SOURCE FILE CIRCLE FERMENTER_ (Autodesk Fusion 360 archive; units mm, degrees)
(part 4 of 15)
sketch "Schizzo1" plane through (-156.8, 0, 0) normal (-1, 0, 0) x axis (0, -1, 0)
  curve K1 (43.7015, -77.2094) -> (43.1419, -79.5252)
  curve K2 (45.0581, -79.5252) -> (44.4985, -77.2094)
  curve K3 (79.8015, 15.4906) -> (79.2419, 13.1748)
  curve K4 (81.1581, 13.1748) -> (80.5985, 15.4906)
  curve K5 (43.7015, 108.1906) -> (43.1419, 105.8748)
  curve K6 (45.0581, 105.8748) -> (44.4985, 108.1906)
  curve K7 (-0.3985, -77.2094) -> (-0.9581, -79.5252)
  curve K8 (0.9581, -79.5252) -> (0.3985, -77.2094)
  curve K9 (-44.4985, -77.2094) -> (-45.0581, -79.5252)
  curve K10 (-43.1419, -79.5252) -> (-43.7015, -77.2094)
  curve K11 (-44.4985, 108.1906) -> (-45.0581, 105.8748)
  curve K12 (-43.1419, 105.8748) -> (-43.7015, 108.1906)
  curve K13 (-0.3985, 108.1906) -> (-0.9581, 105.8748)
  curve K14 (0.9581, 105.8748) -> (0.3985, 108.1906)
  curve K15 (-80.5985, 15.4906) -> (-81.1581, 13.1748)
  curve K16 (-79.2419, 13.1748) -> (-79.8015, 15.4906)
  line L1 (65, 103.7507) -> (-65, 103.7507)
  curve K17 (77.2507, 91.5) -> (65, 103.7507)
  line L2 (77.2507, -63.5) -> (77.2507, 91.5)
  curve K18 (65, -75.7507) -> (77.2507, -63.5)
  line L3 (-65, -75.7507) -> (65, -75.7507)
  curve K19 (-77.2507, -63.5) -> (-65, -75.7507)
  line L4 (-77.2507, 91.5) -> (-77.2507, -63.5)
  curve K20 (-65, 103.7507) -> (-77.2507, 91.5)
  line L5 (-65, 111.4507) -> (65, 111.4507)
  curve K21 (-84.9507, 91.5) -> (-65, 111.4507)
  line L6 (-84.9507, -63.5) -> (-84.9507, 91.5)
  curve K22 (-65, -83.4507) -> (-84.9507, -63.5)
  line L7 (65, -83.4507) -> (-65, -83.4507)
  curve K23 (84.9507, -63.5) -> (65, -83.4507)
  line L8 (84.9507, 91.5) -> (84.9507, -63.5)
  curve K24 (65, 111.4507) -> (84.9507, 91.5)
  arc A1 centre (44.1, -78.7) radius 1.2645 clockwise from (45.0581, -79.5252) to (43.1419, -79.5252)
  arc A2 centre (80.2, 14) radius 1.2645 clockwise from (81.1581, 13.1748) to (79.2419, 13.1748)
  arc A3 centre (44.1, 106.7) radius 1.2645 clockwise from (45.0581, 105.8748) to (43.1419, 105.8748)
  arc A4 centre (0, -78.7) radius 1.2645 clockwise from (0.9581, -79.5252) to (-0.9581, -79.5252)
  arc A5 centre (-44.1, -78.7) radius 1.2645 clockwise from (-43.1419, -79.5252) to (-45.0581, -79.5252)
  arc A6 centre (-44.1, 106.7) radius 1.2645 clockwise from (-43.1419, 105.8748) to (-45.0581, 105.8748)
  arc A7 centre (0, 106.7) radius 1.2645 clockwise from (0.9581, 105.8748) to (-0.9581, 105.8748)
  arc A8 centre (-80.2, 14) radius 1.2645 clockwise from (-79.2419, 13.1748) to (-81.1581, 13.1748)
  circle C1 centre (81.5735, 71.5) radius 1.75
  circle C2 centre (81.5735, 71.5) radius 1.75
  circle C3 centre (81.5735, -43.5) radius 1.75
  circle C4 centre (-81.5735, -43.5) radius 1.75
  circle C5 centre (-81.5735, -43.5) radius 1.75
  circle C6 centre (-81.5735, 71.5) radius 1.75
  circle C7 centre (-81.5735, 71.5) radius 1.75
  arc A9 centre (-80.2, 14) radius 1.543 clockwise from (-80.5985, 15.4906) to (-79.8015, 15.4906)
  arc A10 centre (0, 106.7) radius 1.543 clockwise from (-0.3985, 108.1906) to (0.3985, 108.1906)
  arc A11 centre (-44.1, 106.7) radius 1.543 clockwise from (-44.4985, 108.1906) to (-43.7015, 108.1906)
  arc A12 centre (-44.1, -78.7) radius 1.543 clockwise from (-44.4985, -77.2094) to (-43.7015, -77.2094)
  arc A13 centre (0, -78.7) radius 1.543 clockwise from (-0.3985, -77.2094) to (0.3985, -77.2094)
  arc A14 centre (44.1, 106.7) radius 1.543 clockwise from (43.7015, 108.1906) to (44.4985, 108.1906)
  arc A15 centre (80.2, 14) radius 1.543 clockwise from (79.8015, 15.4906) to (80.5985, 15.4906)
  arc A16 centre (44.1, -78.7) radius 1.543 clockwise from (43.7015, -77.2094) to (44.4985, -77.2094)
extrude "Estrusione1" cut sketch "Schizzo1" profile of C1 C2 C3 C4 C5 C6 C7 against normal blind 3
offset_faces "FacceDiOffset1" distance -0.5
sketch "Schizzo2" plane through (0, 0, -63.5) normal (0, 0, -1) x axis (-1, 0, 0)
  line L1 (156.8, -77.2507) -> (156.8, -84.9507)
  line L2 (156.8, 84.9507) -> (156.8, 77.2507)
  line L3 (180, 88.4) -> (160, 88.4)
  line L4 (153.8, 84.9507) -> (156.8, 84.9507)
  curve K1 (160, 86.8) -> (153.8, 85.2507)
  line L5 (160, -86.8) -> (160, -88.4)
  line L6 (160, 88.4) -> (160, 86.8)
  curve K2 (160, 86.55) -> (153.9051, 85.0239)
  line L7 (153.9051, 85.0239) -> (153.8, 84.9507)
  line L8 (160, 88.4) -> (160, 86.55)
  line L9 (156.8, 77.2507) -> (153.8, 77.2507)
  curve K3 (157.8, 77.2507) -> (153.8, 77.2507)
  curve K4 (160.8, 82.6455) -> (157.8, 77.2507)
  curve K5 (164, 88.4) -> (160.8, 82.6455)
  curve K6 (168, 88.4) -> (164, 88.4)
  curve K7 (168, 88.4) -> (153.8, 77.2507)
  line L10 (156.8, 77.2507) -> (153.8, 77.2507)
  line L11 (156.8, 78.3845) -> (156.8, 77.2507)
  point P9 (153.8, 84.9507)
  point P18 (153.8, 84.9507)
  point P6 (160, 88.4)
  point P19 (160, 88.4)
  point P24 (164, 88.4)
  point P25 (168, 88.4)
  point P20 (153.8, 77.2507)
  point P26 (153.8, 77.2507)
  point P21 (156.8, 77.2507)
  point P27 (156.8, 77.2507)
  point P4 (156.8, 77.2507)
  point P28 (156.8, 77.2507)
  point P29 (156.8, 78.3845)
  point P22 (157.8, 77.2507)
  point P23 (160.8, 82.6455)
  coincident P9 P18
  coincident P6 P19
  perpendicular L3 L8
  coincident L3 P24
  coincident L3 P25
  horizontal K3
  parallel K4 K5
  coincident P20 P26
  coincident P21 P27
  coincident P4 P28
  coincident K7 P29
  coincident L2 P29
  dimension "d1011" = 0.25
  dimension "d1014" distance P20 P22 = 4
  dimension "d1015" distance P24 P25 = 4
  dimension "d1016" distance P19 P24 = 4
  dimension "d1017" distance P22 P24 = 11.1493
  dimension "d1018" distance L2 P23 = 4
sweep "Sweep1" sketch "Schizzo2" TwistAngle 0 TaperAngle 0
sweep "Sweep2" sketch "Schizzo2" TwistAngle 0 TaperAngle 0
remove_body "RimuoviCorpo4"
sketch "Schizzo3" plane through (-160, 0, 0) normal (-1, 0, 0) x axis (0, -1, 0)
  line L1 (-65, 116.5) -> (65, 116.5)
  curve K1 (-65, 116.5) -> (-90, 91.5)
  line L2 (-90, -63.5) -> (-90, 91.5)
  curve K2 (-65, -88.5) -> (-90, -63.5)
  line L3 (65, -88.5) -> (-65, -88.5)
  curve K3 (65, -88.5) -> (90, -63.5)
  line L4 (90, 91.5) -> (90, -63.5)
  curve K4 (65, 116.5) -> (90, 91.5)
  line L5 (65, 114.9) -> (-65, 114.9)
  curve K5 (88.4, 91.5) -> (65, 114.9)
  line L6 (88.4, -63.5) -> (88.4, 91.5)
  curve K6 (88.4, -63.5) -> (65, -86.9)
  line L7 (-65, -86.9) -> (65, -86.9)
  curve K7 (-88.4, -63.5) -> (-65, -86.9)
  line L8 (-88.4, 91.5) -> (-88.4, -63.5)
  curve K8 (-88.4, 91.5) -> (-65, 114.9)
extrude "Estrusione2" add sketch "Schizzo3" along normal blind 20
chamfer "Smusso1" distance 0.8
sketch "Schizzo4" plane through (-148.4, 0, 0) normal (1, 0, 0) x axis (0, 1, 0)
  curve K1 (65, 110.4651) -> (83.9651, 91.5)
  line L1 (-65, 110.4651) -> (65, 110.4651)
  curve K2 (-83.9651, 91.5) -> (-65, 110.4651)
  line L2 (-83.9651, -63.5) -> (-83.9651, 91.5)
  curve K3 (-65, -82.4651) -> (-83.9651, -63.5)
  line L3 (65, -82.4651) -> (-65, -82.4651)
  curve K4 (83.9651, -63.5) -> (65, -82.4651)
  line L4 (83.9651, 91.5) -> (83.9651, -63.5)
  curve K5 (-76.5, -63.5) -> (-65, -75)
  line L5 (-76.5, 91.5) -> (-76.5, -63.5)
  curve K6 (-65, 103) -> (-76.5, 91.5)
  line L6 (65, 103) -> (-65, 103)
  curve K7 (76.5, 91.5) -> (65, 103)
  line L7 (76.5, -63.5) -> (76.5, 91.5)
  curve K8 (65, -75) -> (76.5, -63.5)
  line L8 (-65, -75) -> (65, -75)
  circle C1 centre (-44.1, -78.7) radius 3.35
  circle C2 centre (44.1, -78.7) radius 3.35
  circle C3 centre (0, -78.7) radius 3.35
  circle C4 centre (-44.1, 106.7) radius 3.35
  circle C5 centre (-80.2, 14) radius 3.35
  circle C6 centre (44.1, 106.7) radius 3.35
  circle C7 centre (0, 106.7) radius 3.35
  circle C8 centre (80.2, 14) radius 3.35
  circle C9 centre (-81.5735, 71.5) radius 1.75
  circle C10 centre (81.5735, 71.5) radius 1.75
  circle C11 centre (-81.5735, -43.5) radius 1.75
  circle C12 centre (81.5735, -43.5) radius 1.75
extrude "Estrusione3" cut sketch "Schizzo4" profile of C9 C10 C11 C12 against normal blind 75.727
work_plane "Piano di lavoro1" AlongDistance 3
remove_body "RimuoviCorpo6"
work_plane "Piano di lavoro2" AlongDistance -25
sketch "Schizzo7" plane through (0, 0, -63.5) normal (0, 0, -1) x axis (-1, 0, 0)
  line L1 (180, 88.4) -> (168, 88.4)
  curve K1 (168, 88.4) -> (156.8, 78.3845)
  curve K2 (156.8, 78.3845) -> (153.8, 77.2507)
  line L2 (180, 81.4) -> (180, 88.4)
  curve K3 (177, 81.4) -> (180, 81.4)
  curve K4 (174, 84.9) -> (177, 81.4)
  curve K5 (171, 88.4) -> (174, 84.9)
  curve K6 (168, 88.4) -> (171, 88.4)
  curve K7 (168, 88.4) -> (180, 81.4)
  point P11 (171, 88.4)
  point P3 (180, 88.4)
  point P12 (180, 88.4)
  point P8 (180, 81.4)
  point P9 (177, 81.4)
  point P5 (168, 88.4)
  point P10 (174, 84.9)
  perpendicular L1 L2
  coincident L1 P11
  horizontal K3
  parallel K4 K5
  coincident P3 P12
  dimension "d1051" distance P3 P8 = 7
  dimension "d1052" distance P8 P9 = 3
  dimension "d1053" distance P5 P11 = 3
  dimension "d1054" distance P10 K3 = 3.5 (= "d1051 / 2")
sketch "Schizzo6" plane through (-180, 0, 0) normal (-1, 0, 0) x axis (0, -1, 0)
  line L1 (65, 114.9) -> (-65, 114.9)
  curve K1 (88.4, 91.5) -> (65, 114.9)
  line L2 (88.4, -63.5) -> (88.4, 91.5)
  curve K2 (65, -86.9) -> (88.4, -63.5)
  line L3 (-65, -86.9) -> (65, -86.9)
  curve K3 (-88.4, -63.5) -> (-65, -86.9)
  line L4 (-88.4, 91.5) -> (-88.4, -63.5)
  curve K4 (-65, 114.9) -> (-88.4, 91.5)
  line L5 (90, 91.5) -> (90, -63.5)
  curve K5 (65, 116.5) -> (90, 91.5)
  line L6 (-65, 116.5) -> (65, 116.5)
  curve K6 (-90, 91.5) -> (-65, 116.5)
  line L7 (-90, -63.5) -> (-90, 91.5)
  curve K7 (-65, -88.5) -> (-90, -63.5)
  line L8 (65, -88.5) -> (-65, -88.5)
  curve K8 (90, -63.5) -> (65, -88.5)
  line L9 (-81.5735, 68.5) -> (-81.5735, 74.5)
  line L10 (-88.4, 60.4309) -> (-79.4522, 69.3787)
  line L11 (-88.4, 82.5691) -> (-79.4522, 73.6213)
  line L12 (-6.0795, 14) -> (-90, 14)
  line L13 (-88.4, -54.5691) -> (-79.4522, -45.6213)
  line L14 (-88.4, -32.4309) -> (-79.4522, -41.3787)
  circle C1 centre (-81.5735, -43.5) radius 1.75
  circle C2 centre (-81.5735, 71.5) radius 1.75
  arc A1 centre (-81.5735, 71.5) radius 3 clockwise from (-79.4522, 73.6213) to (-79.4522, 69.3787)
  arc A2 centre (-81.5735, -43.5) radius 3 clockwise from (-79.4522, -41.3787) to (-79.4522, -45.6213)
  point P20 (-81.5735, 71.5)
  point P24 (-88.4, 60.4309)
  point P26 (-88.4, 82.5691)
  point P27 (-90, 14)
  point P23 (-79.4522, 69.3787)
  point P32 (-79.4522, -41.3787)
  point P33 (-88.4, -32.4309)
  point P25 (-79.4522, 73.6213)
  point P29 (-79.4522, -45.6213)
  point P30 (-88.4, -54.5691)
  concentric C2 A1
  vertical L9
  coincident P20 L9
  coincident L4 P24
  coincident L4 P26
  tangent L11 A1
  tangent L10 A1
  midpoint L7 P27
  perpendicular L4 L12
  symmetric P23 L12 P32
  symmetric P24 L12 P33
  symmetric P25 L12 P29
  symmetric P26 L12 P30
  symmetric A1 L12 A2
  dimension "d1043" diameter A1 = 6
  dimension "d1044" angle L9 L10 = 135
  dimension "d1045" angle L9 L11 = 135
extrude "Estrusione5" add sketch "Schizzo6" profile of L4 C1 C2 A1 L10 L11 L13 A2 L14 to an object
mirror "Specchio1" mirrorStitchTolerance 0.1
sweep "Sweep3" sketch "Schizzo7" TwistAngle 0 TaperAngle 0
sketch "Schizzo8" plane through (-153.8, 0, 0) normal (1, 0, 0) x axis (0, 1, 0)
  line L1 (-84.9507, -63.5) -> (-84.9507, 91.5)
  curve K1 (-65, -83.4507) -> (-84.9507, -63.5)
  line L2 (65, -83.4507) -> (-65, -83.4507)
  curve K2 (84.9507, -63.5) -> (65, -83.4507)
  line L3 (84.9507, 91.5) -> (84.9507, -63.5)
  curve K3 (65, 111.4507) -> (84.9507, 91.5)
  line L4 (-65, 111.4507) -> (65, 111.4507)
  curve K4 (-84.9507, 91.5) -> (-65, 111.4507)
  curve K5 (81.1581, 13.1748) -> (80.5985, 15.4906)
  curve K6 (79.8015, 15.4906) -> (79.2419, 13.1748)
  curve K7 (-43.1419, -79.5252) -> (-43.7015, -77.2094)
  curve K8 (-44.4985, -77.2094) -> (-45.0581, -79.5252)
  curve K9 (0.9581, 105.8748) -> (0.3985, 108.1906)
  curve K10 (-0.3985, 108.1906) -> (-0.9581, 105.8748)
  curve K11 (0.9581, -79.5252) -> (0.3985, -77.2094)
  curve K12 (-0.3985, -77.2094) -> (-0.9581, -79.5252)
  curve K13 (-79.2419, 13.1748) -> (-79.8015, 15.4906)
  curve K14 (-80.5985, 15.4906) -> (-81.1581, 13.1748)
  curve K15 (-43.1419, 105.8748) -> (-43.7015, 108.1906)
  curve K16 (-44.4985, 108.1906) -> (-45.0581, 105.8748)
  curve K17 (45.0581, 105.8748) -> (44.4985, 108.1906)
  curve K18 (43.7015, 108.1906) -> (43.1419, 105.8748)
  curve K19 (45.0581, -79.5252) -> (44.4985, -77.2094)
  curve K20 (43.7015, -77.2094) -> (43.1419, -79.5252)
  line L5 (65, 103.7507) -> (-65, 103.7507)
  curve K21 (65, 103.7507) -> (77.2507, 91.5)
  line L6 (77.2507, -63.5) -> (77.2507, 91.5)
  curve K22 (77.2507, -63.5) -> (65, -75.7507)
  line L7 (-65, -75.7507) -> (65, -75.7507)
  curve K23 (-65, -75.7507) -> (-77.2507, -63.5)
  line L8 (-77.2507, 91.5) -> (-77.2507, -63.5)
  curve K24 (-77.2507, 91.5) -> (-65, 103.7507)
  circle C1 centre (-81.5735, 71.5) radius 2.25
  circle C2 centre (-81.5735, -43.5) radius 2.25
  circle C3 centre (81.5735, 71.5) radius 2.25
  circle C4 centre (81.5735, -43.5) radius 2.25
  arc A1 centre (80.2, 14) radius 1.2645 clockwise from (81.1581, 13.1748) to (79.2419, 13.1748)
  arc A2 centre (-44.1, -78.7) radius 1.2645 clockwise from (-43.1419, -79.5252) to (-45.0581, -79.5252)
  arc A3 centre (0, 106.7) radius 1.2645 clockwise from (0.9581, 105.8748) to (-0.9581, 105.8748)
  arc A4 centre (0, -78.7) radius 1.2645 clockwise from (0.9581, -79.5252) to (-0.9581, -79.5252)
  arc A5 centre (-80.2, 14) radius 1.2645 clockwise from (-79.2419, 13.1748) to (-81.1581, 13.1748)
  arc A6 centre (-44.1, 106.7) radius 1.2645 clockwise from (-43.1419, 105.8748) to (-45.0581, 105.8748)
  arc A7 centre (44.1, 106.7) radius 1.2645 clockwise from (45.0581, 105.8748) to (43.1419, 105.8748)
  arc A8 centre (44.1, -78.7) radius 1.2645 clockwise from (45.0581, -79.5252) to (43.1419, -79.5252)
  circle C5 centre (81.5735, -43.5) radius 1.75
  circle C6 centre (81.5735, 71.5) radius 1.75
  circle C7 centre (-81.5735, 71.5) radius 1.75
  circle C8 centre (-81.5735, 71.5) radius 2.25
  circle C9 centre (-81.5735, -43.5) radius 2.25
  circle C10 centre (-81.5735, -43.5) radius 1.75
  circle C11 centre (81.5735, -43.5) radius 2.25
  circle C12 centre (81.5735, 71.5) radius 2.25
  arc A9 centre (44.1, -78.7) radius 1.543 clockwise from (43.7015, -77.2094) to (44.4985, -77.2094)
  arc A10 centre (-44.1, 106.7) radius 1.543 clockwise from (-44.4985, 108.1906) to (-43.7015, 108.1906)
  arc A11 centre (0, 106.7) radius 1.543 clockwise from (-0.3985, 108.1906) to (0.3985, 108.1906)
  arc A12 centre (-80.2, 14) radius 1.543 clockwise from (-80.5985, 15.4906) to (-79.8015, 15.4906)
  arc A13 centre (80.2, 14) radius 1.543 clockwise from (79.8015, 15.4906) to (80.5985, 15.4906)
  arc A14 centre (44.1, 106.7) radius 1.543 clockwise from (43.7015, 108.1906) to (44.4985, 108.1906)
  arc A15 centre (0, -78.7) radius 1.543 clockwise from (-0.3985, -77.2094) to (0.3985, -77.2094)
  arc A16 centre (-44.1, -78.7) radius 1.543 clockwise from (-44.4985, -77.2094) to (-43.7015, -77.2094)
extrude "Estrusione6" cut sketch "Schizzo8" profile of C5 C6 C7 C10 against normal blind 84.147
extrude "Estrusione7" add sketch "Schizzo8" profile of C1 C2 C3 C4 C5 C6 C7 C8 C9 C10 C11 C12 against normal blind 3.228
fillet "Raccordo1" radius 3
sketch "Schizzo1" plane through (-180, 0, 0) normal (-1, 0, 0) x axis (0, -1, 0)
  line L1 (79.4522, 73.6213) -> (80.5213, 74.6904)
  line L2 (80.5213, 68.3096) -> (79.4522, 69.3787)
  curve K1 (80.5213, 68.3096) -> (81.4, 66.1882)
  line L3 (81.4, -38.1882) -> (81.4, 66.1882)
  curve K2 (81.4, -38.1882) -> (80.5213, -40.3096)
  line L4 (79.4522, -41.3787) -> (80.5213, -40.3096)
  line L5 (80.5213, -46.6904) -> (79.4522, -45.6213)
  curve K3 (80.5213, -46.6904) -> (81.4, -48.8118)
  line L6 (81.4, -63.5) -> (81.4, -48.8118)
  curve K4 (81.4, -63.5) -> (65, -79.9)
  line L7 (-65, -79.9) -> (65, -79.9)
  curve K5 (-65, -79.9) -> (-81.4, -63.5)
  line L8 (-81.4, -48.8118) -> (-81.4, -63.5)
  curve K6 (-81.4, -48.8118) -> (-80.5213, -46.6904)
  line L9 (-79.4522, -45.6213) -> (-80.5213, -46.6904)
  line L10 (-80.5213, -40.3096) -> (-79.4522, -41.3787)
  curve K7 (-80.5213, -40.3096) -> (-81.4, -38.1882)
  line L11 (-81.4, 66.1882) -> (-81.4, -38.1882)
  curve K8 (-81.4, 66.1882) -> (-80.5213, 68.3096)
  line L12 (-79.4522, 69.3787) -> (-80.5213, 68.3096)
  line L13 (-80.5213, 74.6904) -> (-79.4522, 73.6213)
  curve K9 (-80.5213, 74.6904) -> (-81.4, 76.8118)
  line L14 (-81.4, 91.5) -> (-81.4, 76.8118)
  curve K10 (-81.4, 91.5) -> (-65, 107.9)
  line L15 (65, 107.9) -> (-65, 107.9)
  curve K11 (65, 107.9) -> (81.4, 91.5)
  line L16 (81.4, 76.8118) -> (81.4, 91.5)
  curve K12 (81.4, 76.8118) -> (80.5213, 74.6904)
  line L17 (90, 91.5) -> (90, -63.5)
  curve K13 (65, 116.5) -> (90, 91.5)
  line L18 (-65, 116.5) -> (65, 116.5)
  curve K14 (-90, 91.5) -> (-65, 116.5)
  line L19 (-90, -63.5) -> (-90, 91.5)
  curve K15 (-65, -88.5) -> (-90, -63.5)
  line L20 (65, -88.5) -> (-65, -88.5)
  curve K16 (90, -63.5) -> (65, -88.5)
  line L21 (-36.4, 59.4) -> (36.4, 59.4)
  line L22 (-42.4, -25.4) -> (-42.4, 53.4)
  line L23 (36.4, -31.4) -> (-36.4, -31.4)
  line L24 (42.4, 53.4) -> (42.4, -25.4)
  line L25 (0, -88.5) -> (0, 116.5)
  line L26 (-42.9, -25.4) -> (-42.9, 53.4)
  line L27 (36.4, -31.9) -> (-36.4, -31.9)
  line L28 (42.9, 53.4) -> (42.9, -25.4)
  line L29 (-36.4, 59.9) -> (36.4, 59.9)
  line L30 (65, -86.5) -> (-65, -86.5)
  curve K17 (88, -63.5) -> (65, -86.5)
  line L31 (88, 91.5) -> (88, -63.5)
  curve K18 (65, 114.5) -> (88, 91.5)
  line L32 (-65, 114.5) -> (65, 114.5)
  line L33 (88, 82.1691) -> (80.5213, 74.6904)
  line L34 (88, 60.8309) -> (80.5213, 68.3096)
  line L35 (88, -32.8309) -> (80.5213, -40.3096)
  line L36 (88, -54.1691) -> (80.5213, -46.6904)
  arc A1 centre (81.5735, 71.5) radius 3 clockwise from (79.4522, 69.3787) to (79.4522, 73.6213)
  arc A2 centre (81.5735, -43.5) radius 3 clockwise from (79.4522, -45.6213) to (79.4522, -41.3787)
  arc A3 centre (-81.5735, -43.5) radius 3 clockwise from (-79.4522, -41.3787) to (-79.4522, -45.6213)
  arc A4 centre (-81.5735, 71.5) radius 3 clockwise from (-79.4522, 73.6213) to (-79.4522, 69.3787)
  circle C1 centre (81.5735, -43.5) radius 1.75
  circle C2 centre (-81.5735, -43.5) radius 1.75
  circle C3 centre (-81.5735, 71.5) radius 1.75
  circle C4 centre (81.5735, 71.5) radius 1.75
  arc A5 centre (-36.4, 53.4) radius 6 clockwise from (-42.4, 53.4) to (-36.4, 59.4)
  arc A6 centre (-36.4, -25.4) radius 6 clockwise from (-36.4, -31.4) to (-42.4, -25.4)
  arc A7 centre (36.4, -25.4) radius 6 clockwise from (42.4, -25.4) to (36.4, -31.4)
  arc A8 centre (36.4, 53.4) radius 6 clockwise from (36.4, 59.4) to (42.4, 53.4)
  arc A9 centre (-36.4, -25.4) radius 6.5 clockwise from (-36.4, -31.9) to (-42.9, -25.4)
  arc A10 centre (36.4, -25.4) radius 6.5 clockwise from (42.9, -25.4) to (36.4, -31.9)
  arc A11 centre (36.4, 53.4) radius 6.5 clockwise from (36.4, 59.9) to (42.9, 53.4)
  arc A12 centre (-36.4, 53.4) radius 6.5 clockwise from (-42.9, 53.4) to (-36.4, 59.9)
  point P58 (0, 116.5)
  point P59 (0, -88.5)
  point P2 (80.5213, 74.6904)
  point P78 (80.5213, 74.6904)
  point P79 (88, 82.1691)
  point P6 (80.5213, 68.3096)
  point P80 (80.5213, 68.3096)
  point P81 (88, 60.8309)
  point P9 (80.5213, -40.3096)
  point P82 (80.5213, -40.3096)
  point P83 (88, -32.8309)
  point P13 (80.5213, -46.6904)
  point P84 (80.5213, -46.6904)
  point P85 (88, -54.1691)
  midpoint L18 P58
  midpoint L20 P59
  coincident P2 P78
  coincident L31 P79
  coincident P6 P80
  coincident L31 P81
  coincident P9 P82
  coincident L31 P83
  coincident P13 P84
  coincident L31 P85
  dimension "d1067" = 0.5
  dimension "d1068" = -2
extrude "Estrusione1" new body sketch "Schizzo1" profile of L1 A1 L2 L4 A2 L5 L25 L28 L27 A10 A11 L29 K17 L30 L31 K18 L32 L33 L34 L35 L36 along normal blind 3
fillet "Raccordo1" radius 5
sketch "Schizzo2" plane through (-183, 0, 0) normal (-1, 0, 0) x axis (0, -1, 0)
  line L1 (79.4522, -45.6213) -> (86.5355, -52.7047)
  line L2 (86.5355, -34.2953) -> (79.4522, -41.3787)
  line L3 (88, 58.7598) -> (88, -30.7598)
  line L4 (79.4522, 69.3787) -> (86.5355, 62.2953)
  line L5 (86.5355, 80.7047) -> (79.4522, 73.6213)
  line L6 (88, 91.5) -> (88, 84.2402)
  curve K1 (65, 114.5) -> (88, 91.5)
  line L7 (0, 114.5) -> (65, 114.5)
  line L8 (0, 59.9) -> (0, 114.5)
  line L9 (36.4, 59.9) -> (0, 59.9)
  line L10 (42.9, -25.4) -> (42.9, 53.4)
  line L11 (0, -31.9) -> (36.4, -31.9)
  line L12 (0, -86.5) -> (0, -31.9)
  line L13 (65, -86.5) -> (0, -86.5)
  curve K2 (88, -63.5) -> (65, -86.5)
  line L14 (88, -56.2402) -> (88, -63.5)
  line L15 (79.4522, 73.6213) -> (80.5213, 74.6904)
  line L16 (80.5213, 68.3096) -> (79.4522, 69.3787)
  curve K3 (80.5213, 68.3096) -> (81.4, 66.1882)
  line L17 (81.4, -38.1882) -> (81.4, 66.1882)
  curve K4 (81.4, -38.1882) -> (80.5213, -40.3096)
  line L18 (79.4522, -41.3787) -> (80.5213, -40.3096)
  line L19 (80.5213, -46.6904) -> (79.4522, -45.6213)
  curve K5 (80.5213, -46.6904) -> (81.4, -48.8118)
  line L20 (81.4, -63.5) -> (81.4, -48.8118)
  curve K6 (81.4, -63.5) -> (65, -79.9)
  line L21 (-65, -79.9) -> (65, -79.9)
  curve K7 (-65, -79.9) -> (-81.4, -63.5)
  line L22 (-81.4, -48.8118) -> (-81.4, -63.5)
  curve K8 (-81.4, -48.8118) -> (-80.5213, -46.6904)
  line L23 (-79.4522, -45.6213) -> (-80.5213, -46.6904)
  line L24 (-80.5213, -40.3096) -> (-79.4522, -41.3787)
  curve K9 (-80.5213, -40.3096) -> (-81.4, -38.1882)
  line L25 (-81.4, 66.1882) -> (-81.4, -38.1882)
  curve K10 (-81.4, 66.1882) -> (-80.5213, 68.3096)
  line L26 (-79.4522, 69.3787) -> (-80.5213, 68.3096)
  line L27 (-80.5213, 74.6904) -> (-79.4522, 73.6213)
  curve K11 (-80.5213, 74.6904) -> (-81.4, 76.8118)
  line L28 (-81.4, 91.5) -> (-81.4, 76.8118)
  curve K12 (-81.4, 91.5) -> (-65, 107.9)
  line L29 (65, 107.9) -> (-65, 107.9)
  curve K13 (65, 107.9) -> (81.4, 91.5)
  line L30 (81.4, 76.8118) -> (81.4, 91.5)
  curve K14 (81.4, 76.8118) -> (80.5213, 74.6904)
  line L31 (90, 91.5) -> (90, -63.5)
  curve K15 (65, 116.5) -> (90, 91.5)
  line L32 (-65, 116.5) -> (65, 116.5)
  curve K16 (-90, 91.5) -> (-65, 116.5)
  line L33 (-90, -63.5) -> (-90, 91.5)
  curve K17 (-65, -88.5) -> (-90, -63.5)
  line L34 (65, -88.5) -> (-65, -88.5)
  curve K18 (90, -63.5) -> (65, -88.5)
  curve K19 (65, 110.9) -> (84.4, 91.5)
  line L35 (65, 110.9) -> (-65, 110.9)
  curve K20 (-84.4, 91.5) -> (-65, 110.9)
  line L36 (-84.4, 91.5) -> (-84.4, 76.8118)
  curve K21 (-82.6426, 72.5691) -> (-84.4, 76.8118)
  line L37 (-82.6426, 72.5691) -> (-81.5735, 71.5)
  line L38 (-81.5735, 71.5) -> (-82.6426, 70.4309)
  curve K22 (-84.4, 66.1882) -> (-82.6426, 70.4309)
  line L39 (-84.4, 66.1882) -> (-84.4, -38.1882)
  curve K23 (-82.6426, -42.4309) -> (-84.4, -38.1882)
  line L40 (-82.6426, -42.4309) -> (-81.5735, -43.5)
  line L41 (-81.5735, -43.5) -> (-82.6426, -44.5691)
  curve K24 (-84.4, -48.8118) -> (-82.6426, -44.5691)
  line L42 (-84.4, -48.8118) -> (-84.4, -63.5)
  curve K25 (-65, -82.9) -> (-84.4, -63.5)
  line L43 (-65, -82.9) -> (65, -82.9)
  curve K26 (84.4, -63.5) -> (65, -82.9)
  line L44 (84.4, -63.5) -> (84.4, -48.8118)
  curve K27 (82.6426, -44.5691) -> (84.4, -48.8118)
  line L45 (82.6426, -44.5691) -> (81.5735, -43.5)
  line L46 (81.5735, -43.5) -> (82.6426, -42.4309)
  curve K28 (84.4, -38.1882) -> (82.6426, -42.4309)
  line L47 (84.4, -38.1882) -> (84.4, 66.1882)
  curve K29 (82.6426, 70.4309) -> (84.4, 66.1882)
  line L48 (82.6426, 70.4309) -> (81.5735, 71.5)
  line L49 (81.5735, 71.5) -> (82.6426, 72.5691)
  curve K30 (84.4, 76.8118) -> (82.6426, 72.5691)
  line L50 (84.4, 76.8118) -> (84.4, 91.5)
  line L51 (-106.4199, 14) -> (88, 14)
  arc A1 centre (83, -56.2402) radius 5 clockwise from (86.5355, -52.7047) to (88, -56.2402)
  arc A2 centre (81.5735, -43.5) radius 3 clockwise from (79.4522, -45.6213) to (79.4522, -41.3787)
  arc A3 centre (83, -30.7598) radius 5 clockwise from (88, -30.7598) to (86.5355, -34.2953)
  arc A4 centre (83, 58.7598) radius 5 clockwise from (86.5355, 62.2953) to (88, 58.7598)
  arc A5 centre (81.5735, 71.5) radius 3 clockwise from (79.4522, 69.3787) to (79.4522, 73.6213)
  arc A6 centre (83, 84.2402) radius 5 clockwise from (88, 84.2402) to (86.5355, 80.7047)
  arc A7 centre (36.4, 53.4) radius 6.5 clockwise from (36.4, 59.9) to (42.9, 53.4)
  arc A8 centre (36.4, -25.4) radius 6.5 clockwise from (42.9, -25.4) to (36.4, -31.9)
  arc A9 centre (81.5735, 71.5) radius 3 clockwise from (79.4522, 69.3787) to (79.4522, 73.6213)
  arc A10 centre (81.5735, -43.5) radius 3 clockwise from (79.4522, -45.6213) to (79.4522, -41.3787)
  arc A11 centre (-81.5735, -43.5) radius 3 clockwise from (-79.4522, -41.3787) to (-79.4522, -45.6213)
  arc A12 centre (-81.5735, 71.5) radius 3 clockwise from (-79.4522, 73.6213) to (-79.4522, 69.3787)
  circle C1 centre (81.5735, -43.5) radius 1.75
  circle C2 centre (-81.5735, -43.5) radius 1.75
  circle C3 centre (-81.5735, 71.5) radius 1.75
  circle C4 centre (81.5735, 71.5) radius 1.75
  point P106 (25, 110.9)
  point P107 (84.4, 39)
  point P108 (88, 14)
  point P110 (25, -82.9)
  point P111 (84.4, -11)
  coincident L35 P106
  coincident L47 P107
  midpoint L3 P108
  perpendicular L47 L51
  symmetric P106 L51 P110
  symmetric P107 L51 P111
  dimension "d1073" = -3
  dimension "d1074" = 50
  dimension "d1075" distance L8 P106 = 25
hole "Foratura1" HoleDepth 12.597 HoleDiameter 3.5 TipAngle 180
mirror "Specchio1" mirrorStitchTolerance 0.1
sketch "Schizzo9" plane through (-183, 0, 0) normal (-1, 0, 0) x axis (0, -1, 0)
  line L1 (65, -86.5) -> (-65, -86.5)
  curve K1 (88, -63.5) -> (65, -86.5)
  line L2 (88, -56.2402) -> (88, -63.5)
  line L3 (79.4522, -45.6213) -> (86.5355, -52.7047)
  line L4 (86.5355, -34.2953) -> (79.4522, -41.3787)
  line L5 (88, 58.7598) -> (88, -30.7598)
  line L6 (79.4522, 69.3787) -> (86.5355, 62.2953)
  line L7 (86.5355, 80.7047) -> (79.4522, 73.6213)
  line L8 (88, 91.5) -> (88, 84.2402)
  curve K2 (65, 114.5) -> (88, 91.5)
  line L9 (-65, 114.5) -> (65, 114.5)
  curve K3 (-65, 114.5) -> (-88, 91.5)
  line L10 (-88, 84.2402) -> (-88, 91.5)
  line L11 (-79.4522, 73.6213) -> (-86.5355, 80.7047)
  line L12 (-86.5355, 62.2953) -> (-79.4522, 69.3787)
  line L13 (-88, -30.7598) -> (-88, 58.7598)
  line L14 (-79.4522, -41.3787) -> (-86.5355, -34.2953)
  line L15 (-86.5355, -52.7047) -> (-79.4522, -45.6213)
  line L16 (-88, -63.5) -> (-88, -56.2402)
  curve K4 (-88, -63.5) -> (-65, -86.5)
  line L17 (-36.4, -31.9) -> (36.4, -31.9)
  line L18 (-42.9, 53.4) -> (-42.9, -25.4)
  line L19 (36.4, 59.9) -> (-36.4, 59.9)
  line L20 (42.9, -25.4) -> (42.9, 53.4)
  arc A1 centre (83, -56.2402) radius 5 clockwise from (86.5355, -52.7047) to (88, -56.2402)
  arc A2 centre (81.5735, -43.5) radius 3 clockwise from (79.4522, -45.6213) to (79.4522, -41.3787)
  arc A3 centre (83, -30.7598) radius 5 clockwise from (88, -30.7598) to (86.5355, -34.2953)
  arc A4 centre (83, 58.7598) radius 5 clockwise from (86.5355, 62.2953) to (88, 58.7598)
  arc A5 centre (81.5735, 71.5) radius 3 clockwise from (79.4522, 69.3787) to (79.4522, 73.6213)
  arc A6 centre (83, 84.2402) radius 5 clockwise from (88, 84.2402) to (86.5355, 80.7047)
  arc A7 centre (-83, 84.2402) radius 5 clockwise from (-86.5355, 80.7047) to (-88, 84.2402)
  arc A8 centre (-81.5735, 71.5) radius 3 clockwise from (-79.4522, 73.6213) to (-79.4522, 69.3787)
  arc A9 centre (-83, 58.7598) radius 5 clockwise from (-88, 58.7598) to (-86.5355, 62.2953)
  arc A10 centre (-83, -30.7598) radius 5 clockwise from (-86.5355, -34.2953) to (-88, -30.7598)
  arc A11 centre (-81.5735, -43.5) radius 3 clockwise from (-79.4522, -41.3787) to (-79.4522, -45.6213)
  arc A12 centre (-83, -56.2402) radius 5 clockwise from (-88, -56.2402) to (-86.5355, -52.7047)
  circle C1 centre (-25, 110.9) radius 1.75
  circle C2 centre (-84.4, -11) radius 1.75
  circle C3 centre (-25, -82.9) radius 1.75
  circle C4 centre (-84.4, 39) radius 1.75
  circle C5 centre (84.4, 39) radius 1.75
  circle C6 centre (25, -82.9) radius 1.75
  circle C7 centre (84.4, -11) radius 1.75
  circle C8 centre (25, 110.9) radius 1.75
  arc A13 centre (-36.4, -25.4) radius 6.5 clockwise from (-36.4, -31.9) to (-42.9, -25.4)
  arc A14 centre (-36.4, 53.4) radius 6.5 clockwise from (-42.9, 53.4) to (-36.4, 59.9)
  arc A15 centre (36.4, 53.4) radius 6.5 clockwise from (36.4, 59.9) to (42.9, 53.4)
  arc A16 centre (36.4, -25.4) radius 6.5 clockwise from (42.9, -25.4) to (36.4, -31.9)
extrude "Estrusione8" cut sketch "Schizzo9" profile of C1 C2 C4 against normal blind 11.8105
sketch "Schizzo7" plane through (-153.8, 0, 0) normal (-1, 0, 0) x axis (0, -1, 0)
  line L1 (20, 10.5) -> (-20, 10.5)
  line L2 (-20, -28.5) -> (20, -28.5)
  line L3 (-20, 22.5) -> (20, 22.5)
  line L4 (20, 47.5) -> (-20, 47.5)
  line L5 (-83.1107, -63.5) -> (-83.1107, -45.4967)
  curve K1 (-65, -81.6107) -> (-83.1107, -63.5)
  line L6 (65, -81.6107) -> (-65, -81.6107)
  curve K2 (83.1107, -63.5) -> (65, -81.6107)
  line L7 (83.1107, -45.4967) -> (83.1107, -63.5)
  line L8 (83.1107, 69.5033) -> (83.1107, -41.5033)
  line L9 (83.1107, 91.5) -> (83.1107, 73.4967)
  curve K3 (65, 109.6107) -> (83.1107, 91.5)
  line L10 (-65, 109.6107) -> (65, 109.6107)
  curve K4 (-83.1107, 91.5) -> (-65, 109.6107)
  line L11 (-83.1107, 73.4967) -> (-83.1107, 91.5)
  line L12 (-83.1107, -41.5033) -> (-83.1107, 69.5033)
  line L13 (0, 106.7) -> (0, 47.5)
  line L14 (10.25, -63.8607) -> (-10.25, -63.8607)
  line L15 (10.25, -49.3607) -> (10.25, -63.8607)
  line L16 (-10.25, -49.3607) -> (10.25, -49.3607)
  line L17 (-10.25, -63.8607) -> (-10.25, -49.3607)
  line L18 (10.25, -49.3607) -> (-10.25, -63.8607)
  line L19 (-10.25, -49.3607) -> (10.25, -63.8607)
  circle C1 centre (-36, 53) radius 1.875
  arc A1 centre (-20, -9) radius 19.5 clockwise from (-20, -28.5) to (-20, 10.5)
  arc A2 centre (20, -9) radius 19.5 clockwise from (20, 10.5) to (20, -28.5)
  circle C2 centre (-36, -25) radius 1.725
  circle C3 centre (36, 53) radius 1.875
  arc A3 centre (-20, 35) radius 12.5 clockwise from (-20, 22.5) to (-20, 47.5)
  arc A4 centre (20, 35) radius 12.5 clockwise from (20, 47.5) to (20, 22.5)
  circle C4 centre (36, -25) radius 1.725
  circle C5 centre (44.1, -78.7) radius 1.75
  circle C6 centre (-44.1, -78.7) radius 1.75
  circle C7 centre (0, -78.7) radius 1.75
  circle C8 centre (44.1, 106.7) radius 1.75
  circle C9 centre (80.2, 14) radius 1.75
  circle C10 centre (-44.1, 106.7) radius 1.75
  circle C11 centre (0, 106.7) radius 1.75
  circle C12 centre (-80.2, 14) radius 1.75
  arc A5 centre (-82.6107, -41.5033) radius 0.5 clockwise from (-82.3802, -41.947) to (-83.1107, -41.5033)
  arc A6 centre (-81.5735, -43.5) radius 1.75 clockwise from (-82.3802, -41.947) to (-82.3802, -45.053)
  arc A7 centre (-82.6107, -45.4967) radius 0.5 clockwise from (-83.1107, -45.4967) to (-82.3802, -45.053)
  arc A8 centre (82.6107, -45.4967) radius 0.5 clockwise from (82.3802, -45.053) to (83.1107, -45.4967)
  arc A9 centre (81.5735, -43.5) radius 1.75 clockwise from (82.3802, -45.053) to (82.3802, -41.947)
  arc A10 centre (82.6107, -41.5033) radius 0.5 clockwise from (83.1107, -41.5033) to (82.3802, -41.947)
  arc A11 centre (82.6107, 69.5033) radius 0.5 clockwise from (82.3802, 69.947) to (83.1107, 69.5033)
  arc A12 centre (81.5735, 71.5) radius 1.75 clockwise from (82.3802, 69.947) to (82.3802, 73.053)
  arc A13 centre (82.6107, 73.4967) radius 0.5 clockwise from (83.1107, 73.4967) to (82.3802, 73.053)
  arc A14 centre (-82.6107, 73.4967) radius 0.5 clockwise from (-82.3802, 73.053) to (-83.1107, 73.4967)
  arc A15 centre (-81.5735, 71.5) radius 1.75 clockwise from (-82.3802, 73.053) to (-82.3802, 69.947)
  arc A16 centre (-82.6107, 69.5033) radius 0.5 clockwise from (-83.1107, 69.5033) to (-82.3802, 69.947)
  point P62 (0, 47.5)
  point P24 (0, 106.7)
  point P63 (0, 106.7)
  point P68 (0, -56.6107)
  point P66 (10.25, -49.3607)
  point P67 (-10.25, -49.3607)
  point P65 (10.25, -63.8607)
  midpoint L4 P62
  coincident P24 P63
  horizontal L14
  perpendicular L14 L15
  parallel L14 L16
  parallel L15 L17
  coincident L18 P68
  coincident L19 P68
  coincident L13 P68
  dimension "d1086" distance P66 P67 = 20.5
  dimension "d1087" distance P65 P66 = 14.5
  dimension "d1102" distance L6 P68 = 25
extrude "Estrusione2" cut sketch "Schizzo7" profile of L14 L15 L16 L17 against normal blind 7.886
component_insert "Inserimento componente2"
joint "Assembla4" alignAngle 0 alignOffsetX 0 alignOffsetY 0 alignOffsetZ 0.25
sketch "Schizzo8" plane through (-153.8, 0, 0) normal (-1, 0, 0) x axis (0, -1, 0)
  line L1 (-10.25, -63.8607) -> (10.25, -63.8607)
  line L2 (-10.25, -49.3607) -> (-10.25, -63.8607)
  line L3 (10.25, -49.3607) -> (-10.25, -49.3607)
  line L4 (10.25, -63.8607) -> (10.25, -49.3607)
  line L5 (20, 10.5) -> (-20, 10.5)
  line L6 (-20, -28.5) -> (20, -28.5)
  line L7 (-20, 22.5) -> (20, 22.5)
  line L8 (20, 47.5) -> (-20, 47.5)
  line L9 (-83.1107, -63.5) -> (-83.1107, -45.4967)
  curve K1 (-65, -81.6107) -> (-83.1107, -63.5)
  line L10 (65, -81.6107) -> (-65, -81.6107)
  curve K2 (83.1107, -63.5) -> (65, -81.6107)
  line L11 (83.1107, -45.4967) -> (83.1107, -63.5)
  line L12 (83.1107, 69.5033) -> (83.1107, -41.5033)
  line L13 (83.1107, 91.5) -> (83.1107, 73.4967)
  curve K3 (65, 109.6107) -> (83.1107, 91.5)
  line L14 (-65, 109.6107) -> (65, 109.6107)
  curve K4 (-83.1107, 91.5) -> (-65, 109.6107)
  line L15 (-83.1107, 73.4967) -> (-83.1107, 91.5)
  line L16 (-83.1107, -41.5033) -> (-83.1107, 69.5033)
  circle C1 centre (-36, 53) radius 1.875
  arc A1 centre (-20, -9) radius 19.5 clockwise from (-20, -28.5) to (-20, 10.5)
  arc A2 centre (20, -9) radius 19.5 clockwise from (20, 10.5) to (20, -28.5)
  circle C2 centre (-36, -25) radius 1.725
  circle C3 centre (36, 53) radius 1.875
  arc A3 centre (-20, 35) radius 12.5 clockwise from (-20, 22.5) to (-20, 47.5)
  arc A4 centre (20, 35) radius 12.5 clockwise from (20, 47.5) to (20, 22.5)
  circle C4 centre (36, -25) radius 1.725
  circle C5 centre (44.1, -78.7) radius 1.75
  circle C6 centre (-44.1, -78.7) radius 1.75
  circle C7 centre (0, -78.7) radius 1.75
  circle C8 centre (44.1, 106.7) radius 1.75
  circle C9 centre (80.2, 14) radius 1.75
  circle C10 centre (-44.1, 106.7) radius 1.75
  circle C11 centre (0, 106.7) radius 1.75
  circle C12 centre (-80.2, 14) radius 1.75
  arc A5 centre (-82.6107, -41.5033) radius 0.5 clockwise from (-82.3802, -41.947) to (-83.1107, -41.5033)
  arc A6 centre (-81.5735, -43.5) radius 1.75 clockwise from (-82.3802, -41.947) to (-82.3802, -45.053)
  arc A7 centre (-82.6107, -45.4967) radius 0.5 clockwise from (-83.1107, -45.4967) to (-82.3802, -45.053)
  arc A8 centre (82.6107, -45.4967) radius 0.5 clockwise from (82.3802, -45.053) to (83.1107, -45.4967)
  arc A9 centre (81.5735, -43.5) radius 1.75 clockwise from (82.3802, -45.053) to (82.3802, -41.947)
  arc A10 centre (82.6107, -41.5033) radius 0.5 clockwise from (83.1107, -41.5033) to (82.3802, -41.947)
  arc A11 centre (82.6107, 69.5033) radius 0.5 clockwise from (82.3802, 69.947) to (83.1107, 69.5033)
  arc A12 centre (81.5735, 71.5) radius 1.75 clockwise from (82.3802, 69.947) to (82.3802, 73.053)
  arc A13 centre (82.6107, 73.4967) radius 0.5 clockwise from (83.1107, 73.4967) to (82.3802, 73.053)
  arc A14 centre (-82.6107, 73.4967) radius 0.5 clockwise from (-82.3802, 73.053) to (-83.1107, 73.4967)
  arc A15 centre (-81.5735, 71.5) radius 1.75 clockwise from (-82.3802, 73.053) to (-82.3802, 69.947)
  arc A16 centre (-82.6107, 69.5033) radius 0.5 clockwise from (-83.1107, 69.5033) to (-82.3802, 69.947)
  circle C13 centre (-12.35, -56.6107) radius 1.55
  circle C14 centre (-12.35, -56.6107) radius 1.75
  concentric C13 C14
  dimension "d1099" diameter C14 = 3.5
extrude "Estrusione3" cut sketch "Schizzo8" profile of C14 against normal blind 3
sketch "Schizzo3" plane through (-183, 0, 0) normal (-1, 0, 0) x axis (0, -1, 0)
  line L1 (65, -86.5) -> (-65, -86.5)
  curve K1 (88, -63.5) -> (65, -86.5)
  line L2 (88, -56.2402) -> (88, -63.5)
  line L3 (79.4522, -45.6213) -> (86.5355, -52.7047)
  line L4 (86.5355, -34.2953) -> (79.4522, -41.3787)
  line L5 (88, 58.7598) -> (88, -30.7598)
  line L6 (79.4522, 69.3787) -> (86.5355, 62.2953)
  line L7 (86.5355, 80.7047) -> (79.4522, 73.6213)
  line L8 (88, 91.5) -> (88, 84.2402)
  curve K2 (65, 114.5) -> (88, 91.5)
  line L9 (-65, 114.5) -> (65, 114.5)
  curve K3 (-65, 114.5) -> (-88, 91.5)
  line L10 (-88, 84.2402) -> (-88, 91.5)
  line L11 (-79.4522, 73.6213) -> (-86.5355, 80.7047)
  line L12 (-86.5355, 62.2953) -> (-79.4522, 69.3787)
  line L13 (-88, -30.7598) -> (-88, 58.7598)
  line L14 (-79.4522, -41.3787) -> (-86.5355, -34.2953)
  line L15 (-86.5355, -52.7047) -> (-79.4522, -45.6213)
  line L16 (-88, -63.5) -> (-88, -56.2402)
  curve K4 (-88, -63.5) -> (-65, -86.5)
  line L17 (-36.4, -31.9) -> (36.4, -31.9)
  line L18 (-42.9, 53.4) -> (-42.9, -25.4)
  line L19 (36.4, 59.9) -> (-36.4, 59.9)
  line L20 (42.9, -25.4) -> (42.9, 53.4)
  line L21 (-42.9, 14) -> (42.9, 14)
  line L22 (0, -31.9) -> (0, 59.9)
  arc A1 centre (83, -56.2402) radius 5 clockwise from (86.5355, -52.7047) to (88, -56.2402)
  arc A2 centre (81.5735, -43.5) radius 3 clockwise from (79.4522, -45.6213) to (79.4522, -41.3787)
  arc A3 centre (83, -30.7598) radius 5 clockwise from (88, -30.7598) to (86.5355, -34.2953)
  arc A4 centre (83, 58.7598) radius 5 clockwise from (86.5355, 62.2953) to (88, 58.7598)
  arc A5 centre (81.5735, 71.5) radius 3 clockwise from (79.4522, 69.3787) to (79.4522, 73.6213)
  arc A6 centre (83, 84.2402) radius 5 clockwise from (88, 84.2402) to (86.5355, 80.7047)
  arc A7 centre (-83, 84.2402) radius 5 clockwise from (-86.5355, 80.7047) to (-88, 84.2402)
  arc A8 centre (-81.5735, 71.5) radius 3 clockwise from (-79.4522, 73.6213) to (-79.4522, 69.3787)
  arc A9 centre (-83, 58.7598) radius 5 clockwise from (-88, 58.7598) to (-86.5355, 62.2953)
  arc A10 centre (-83, -30.7598) radius 5 clockwise from (-86.5355, -34.2953) to (-88, -30.7598)
  arc A11 centre (-81.5735, -43.5) radius 3 clockwise from (-79.4522, -41.3787) to (-79.4522, -45.6213)
  arc A12 centre (-83, -56.2402) radius 5 clockwise from (-88, -56.2402) to (-86.5355, -52.7047)
  circle C1 centre (-25, 110.9) radius 1.75
  circle C2 centre (-84.4, -11) radius 1.75
  circle C3 centre (-25, -82.9) radius 1.75
  circle C4 centre (-84.4, 39) radius 1.75
  circle C5 centre (84.4, 39) radius 1.75
  circle C6 centre (25, -82.9) radius 1.75
  circle C7 centre (84.4, -11) radius 1.75
  circle C8 centre (25, 110.9) radius 1.75
  arc A13 centre (-36.4, -25.4) radius 6.5 clockwise from (-36.4, -31.9) to (-42.9, -25.4)
  arc A14 centre (-36.4, 53.4) radius 6.5 clockwise from (-42.9, 53.4) to (-36.4, 59.9)
  arc A15 centre (36.4, 53.4) radius 6.5 clockwise from (36.4, 59.9) to (42.9, 53.4)
  arc A16 centre (36.4, -25.4) radius 6.5 clockwise from (42.9, -25.4) to (36.4, -31.9)
  circle C9 centre (0, 14) radius 70
  circle C10 centre (0, 14) radius 78
  point P66 (42.9, 14)
  point P67 (-42.9, 14)
  point P68 (0, 59.9)
  point P69 (0, -31.9)
  point P70 (0, 14)
  midpoint L20 P66
  midpoint L18 P67
  midpoint L19 P68
  midpoint L17 P69
  midpoint L21 P70
  dimension "d1103" diameter C9 = 140
  dimension "d1104" = 8
extrude "Estrusione1" sketch "Schizzo3" profile of C9 C10 blind -15
sketch "Schizzo1"
  dimension "d1108" diameter = 148
  dimension "d1109" distance = 0.2
  dimension "d1110" distance = -0.2
  dimension "d1111" distance = 1.6
  dimension "d1113" C-Pattern1-Angle = 360
extrude "Estrusione2" cut sketch "unnamed" blind -12
sketch "Schizzo2" plane through (-177, 0, 0) normal (1, 0, 0) x axis (0, 1, 0)
  line L1 (114.4184, 14) -> (0, 14)
  line L2 (63.0678, -16.3719) -> (0, 14)
  line L3 (69.8048, -1.9325) -> (0, 14)
  line L4 (96.3087, -7.9818) -> (69.8048, -1.9325)
  line L5 (74.9357, -7.6481) -> (70.9793, -3.9772)
  line L6 (76.9075, 0.9909) -> (71.7501, -0.5999)
  line L7 (74.9357, 35.6481) -> (70.9793, 31.9772)
  line L8 (76.9075, 27.0091) -> (71.7501, 28.5999)
  line L9 (58.1219, 66.0177) -> (56.1501, 60.9936)
  line L10 (63.6468, 59.0897) -> (58.31, 58.2853)
  line L11 (29.7964, 86.0845) -> (30.1998, 80.7024)
  line L12 (37.7801, 82.2397) -> (33.3208, 79.1994)
  line L13 (-4.4306, 91.8741) -> (-1.7321, 87.2)
  line L14 (4.4306, 91.8741) -> (1.7321, 87.2)
  line L15 (-37.7801, 82.2397) -> (-33.3208, 79.1994)
  line L16 (-29.7964, 86.0845) -> (-30.1998, 80.7024)
  line L17 (-63.6468, 59.0897) -> (-58.31, 58.2853)
  line L18 (-58.1219, 66.0177) -> (-56.1501, 60.9936)
  line L19 (-76.9075, 27.0091) -> (-71.7501, 28.5999)
  line L20 (-74.9357, 35.6481) -> (-70.9793, 31.9772)
  line L21 (-74.9357, -7.6481) -> (-70.9793, -3.9772)
  line L22 (-76.9075, 0.9909) -> (-71.7501, -0.5999)
  line L23 (-58.1219, -38.0177) -> (-56.1501, -32.9936)
  line L24 (-63.6468, -31.0897) -> (-58.31, -30.2853)
  line L25 (-29.7964, -58.0845) -> (-30.1998, -52.7024)
  line L26 (-37.7801, -54.2397) -> (-33.3208, -51.1994)
  line L27 (4.4306, -63.8741) -> (1.7321, -59.2)
  line L28 (-4.4306, -63.8741) -> (-1.7321, -59.2)
  line L29 (37.7801, -54.2397) -> (33.3208, -51.1994)
  line L30 (29.7964, -58.0845) -> (30.1998, -52.7024)
  line L31 (63.6468, -31.0897) -> (58.31, -30.2853)
  line L32 (58.1219, -38.0177) -> (56.1501, -32.9936)
  arc A1 centre (63.0678, -16.3719) radius 4 clockwise from (66.0311, -13.685) to (62.8147, -20.3638)
  arc A2 centre (0, 14) radius 71.6 clockwise from (62.8147, -20.3638) to (47.4799, -39.5931)
  arc A3 centre (43.6443, -40.7282) radius 4 clockwise from (47.4799, -39.5931) to (41.6842, -44.215)
  arc A4 centre (0, 14) radius 71.6 clockwise from (41.6842, -44.215) to (19.5247, -54.8865)
  arc A5 centre (15.5765, -54.245) radius 4 clockwise from (19.5247, -54.8865) to (12.2976, -56.536)
  arc A6 centre (0, 14) radius 71.6 clockwise from (12.2976, -56.536) to (-12.2976, -56.536)
  arc A7 centre (-15.5765, -54.245) radius 4 clockwise from (-12.2976, -56.536) to (-19.5247, -54.8865)
  arc A8 centre (0, 14) radius 71.6 clockwise from (-19.5247, -54.8865) to (-41.6842, -44.215)
  arc A9 centre (-43.6443, -40.7282) radius 4 clockwise from (-41.6842, -44.215) to (-47.4799, -39.5931)
  arc A10 centre (0, 14) radius 71.6 clockwise from (-47.4799, -39.5931) to (-62.8147, -20.3638)
  arc A11 centre (-63.0678, -16.3719) radius 4 clockwise from (-62.8147, -20.3638) to (-66.0311, -13.685)
  arc A12 centre (0, 14) radius 71.6 clockwise from (-66.0311, -13.685) to (-71.504, 10.2935)
  arc A13 centre (-70, 14) radius 4 clockwise from (-71.504, 10.2935) to (-71.504, 17.7065)
  arc A14 centre (0, 14) radius 71.6 clockwise from (-71.504, 17.7065) to (-66.0311, 41.685)
  arc A15 centre (-63.0678, 44.3719) radius 4 clockwise from (-66.0311, 41.685) to (-62.8147, 48.3638)
  arc A16 centre (0, 14) radius 71.6 clockwise from (-62.8147, 48.3638) to (-47.4799, 67.5931)
  arc A17 centre (-43.6443, 68.7282) radius 4 clockwise from (-47.4799, 67.5931) to (-41.6842, 72.215)
  arc A18 centre (0, 14) radius 71.6 clockwise from (-41.6842, 72.215) to (-19.5247, 82.8865)
  arc A19 centre (-15.5765, 82.245) radius 4 clockwise from (-19.5247, 82.8865) to (-12.2976, 84.536)
  arc A20 centre (0, 14) radius 71.6 clockwise from (-12.2976, 84.536) to (12.2976, 84.536)
  arc A21 centre (15.5765, 82.245) radius 4 clockwise from (12.2976, 84.536) to (19.5247, 82.8865)
  arc A22 centre (0, 14) radius 71.6 clockwise from (19.5247, 82.8865) to (41.6842, 72.215)
  arc A23 centre (43.6443, 68.7282) radius 4 clockwise from (41.6842, 72.215) to (47.4799, 67.5931)
  arc A24 centre (0, 14) radius 71.6 clockwise from (47.4799, 67.5931) to (62.8147, 48.3638)
  arc A25 centre (63.0678, 44.3719) radius 4 clockwise from (62.8147, 48.3638) to (66.0311, 41.685)
  arc A26 centre (0, 14) radius 71.6 clockwise from (66.0311, 41.685) to (71.504, 17.7065)
  arc A27 centre (70, 14) radius 4 clockwise from (71.504, 17.7065) to (71.504, 10.2935)
  arc A28 centre (0, 14) radius 71.6 clockwise from (71.504, 10.2935) to (66.0311, -13.685)
  circle C1 centre (0, 14) radius 78
  arc A29 centre (0, 14) radius 71.6 clockwise from (62.8147, -20.3638) to (47.4799, -39.5931)
  arc A30 centre (63.0678, -16.3719) radius 4 clockwise from (66.0311, -13.685) to (62.8147, -20.3638)
  arc A31 centre (0, 14) radius 71.6 clockwise from (71.504, 10.2935) to (66.0311, -13.685)
  arc A32 centre (70, 14) radius 4 clockwise from (71.504, 17.7065) to (71.504, 10.2935)
  arc A33 centre (0, 14) radius 71.6 clockwise from (66.0311, 41.685) to (71.504, 17.7065)
  arc A34 centre (63.0678, 44.3719) radius 4 clockwise from (62.8147, 48.3638) to (66.0311, 41.685)
  arc A35 centre (0, 14) radius 71.6 clockwise from (47.4799, 67.5931) to (62.8147, 48.3638)
  arc A36 centre (43.6443, 68.7282) radius 4 clockwise from (41.6842, 72.215) to (47.4799, 67.5931)
  arc A37 centre (0, 14) radius 71.6 clockwise from (19.5247, 82.8865) to (41.6842, 72.215)
  arc A38 centre (15.5765, 82.245) radius 4 clockwise from (12.2976, 84.536) to (19.5247, 82.8865)
  arc A39 centre (0, 14) radius 71.6 clockwise from (-12.2976, 84.536) to (12.2976, 84.536)
  arc A40 centre (-15.5765, 82.245) radius 4 clockwise from (-19.5247, 82.8865) to (-12.2976, 84.536)
  arc A41 centre (0, 14) radius 71.6 clockwise from (-41.6842, 72.215) to (-19.5247, 82.8865)
  arc A42 centre (-43.6443, 68.7282) radius 4 clockwise from (-47.4799, 67.5931) to (-41.6842, 72.215)
  arc A43 centre (0, 14) radius 71.6 clockwise from (-62.8147, 48.3638) to (-47.4799, 67.5931)
  arc A44 centre (-63.0678, 44.3719) radius 4 clockwise from (-66.0311, 41.685) to (-62.8147, 48.3638)
  arc A45 centre (0, 14) radius 71.6 clockwise from (-71.504, 17.7065) to (-66.0311, 41.685)
  arc A46 centre (-70, 14) radius 4 clockwise from (-71.504, 10.2935) to (-71.504, 17.7065)
  arc A47 centre (0, 14) radius 71.6 clockwise from (-66.0311, -13.685) to (-71.504, 10.2935)
  arc A48 centre (-63.0678, -16.3719) radius 4 clockwise from (-62.8147, -20.3638) to (-66.0311, -13.685)
  arc A49 centre (0, 14) radius 71.6 clockwise from (-47.4799, -39.5931) to (-62.8147, -20.3638)
  arc A50 centre (-43.6443, -40.7282) radius 4 clockwise from (-41.6842, -44.215) to (-47.4799, -39.5931)
  arc A51 centre (0, 14) radius 71.6 clockwise from (-19.5247, -54.8865) to (-41.6842, -44.215)
  arc A52 centre (-15.5765, -54.245) radius 4 clockwise from (-12.2976, -56.536) to (-19.5247, -54.8865)
  arc A53 centre (0, 14) radius 71.6 clockwise from (12.2976, -56.536) to (-12.2976, -56.536)
  arc A54 centre (15.5765, -54.245) radius 4 clockwise from (19.5247, -54.8865) to (12.2976, -56.536)
  arc A55 centre (0, 14) radius 71.6 clockwise from (41.6842, -44.215) to (19.5247, -54.8865)
  arc A56 centre (43.6443, -40.7282) radius 4 clockwise from (47.4799, -39.5931) to (41.6842, -44.215)
  circle C2 centre (0, 14) radius 70
  arc A57 centre (0, 14) radius 72.2 clockwise from (72.1032, 10.2625) to (66.5844, -13.917)
  arc A58 centre (72.3397, -2.5111) radius 2 clockwise from (70.9793, -3.9772) to (71.7501, -0.5999)
  arc A59 centre (72.3397, 30.5111) radius 2 clockwise from (71.7501, 28.5999) to (70.9793, 31.9772)
  arc A60 centre (58.0119, 60.2629) radius 2 clockwise from (58.31, 58.2853) to (56.1501, 60.9936)
  arc A61 centre (32.1942, 80.8519) radius 2 clockwise from (33.3208, 79.1994) to (30.1998, 80.7024)
  arc A62 centre (0, 88.2) radius 2 clockwise from (1.7321, 87.2) to (-1.7321, 87.2)
  arc A63 centre (-32.1942, 80.8519) radius 2 clockwise from (-30.1998, 80.7024) to (-33.3208, 79.1994)
  arc A64 centre (-58.0119, 60.2629) radius 2 clockwise from (-56.1501, 60.9936) to (-58.31, 58.2853)
  arc A65 centre (-72.3397, 30.5111) radius 2 clockwise from (-70.9793, 31.9772) to (-71.7501, 28.5999)
  arc A66 centre (-72.3397, -2.5111) radius 2 clockwise from (-71.7501, -0.5999) to (-70.9793, -3.9772)
  arc A67 centre (-58.0119, -32.2629) radius 2 clockwise from (-58.31, -30.2853) to (-56.1501, -32.9936)
  arc A68 centre (-32.1942, -52.8519) radius 2 clockwise from (-33.3208, -51.1994) to (-30.1998, -52.7024)
  arc A69 centre (0, -60.2) radius 2 clockwise from (-1.7321, -59.2) to (1.7321, -59.2)
  arc A70 centre (32.1942, -52.8519) radius 2 clockwise from (30.1998, -52.7024) to (33.3208, -51.1994)
  arc A71 centre (58.0119, -32.2629) radius 2 clockwise from (56.1501, -32.9936) to (58.31, -30.2853)
  point P6 (0, 14)
  point P88 (0, 14)
  point P90 (0, 14)
  point P4 (63.0678, -16.3719)
  point P91 (63.0678, -16.3719)
  point P92 (0, 14)
  point P93 (69.8048, -1.9325)
  point P98 (72.3397, -2.5111)
  point P100 (74.9357, -7.6481)
  point P99 (70.9793, -3.9772)
  point P101 (71.7501, -0.5999)
  point P102 (76.9075, 0.9909)
  coincident P6 P88
  horizontal L1
  coincident P6 P90
  coincident P4 P91
  coincident P6 P92
  midpoint A28 P93
  parallel L3 L4
  coincident L4 P98
  tangent A57 A58
  coincident C1 P100
  tangent L5 A58
  symmetric L4 P99 P101
  symmetric L4 P100 P102
  dimension "d1116" = 0.6
  dimension "d1117" diameter A58 = 4
  dimension "d1118" angle L4 L5 = 30
  dimension "d1120" C-Pattern1-Angle = 360
extrude "Estrusione3" add sketch "Schizzo2" profile of C1 A58 L5 L6 L7 A59 L8 L9 A60 L10 L11 A61 L12 L13 A62 L14 L15 A63 L16 L17 A64 L18 L19 A65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 along normal blind 12
fillet "Raccordo1" radius 1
